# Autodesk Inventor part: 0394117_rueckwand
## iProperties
Created: 2005-08
Part Number: 0394117_rueckwand
Document SubType Name: Modellieren
Manufacturer: Standard
Standards Organization: Custom
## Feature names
1. Basis1
